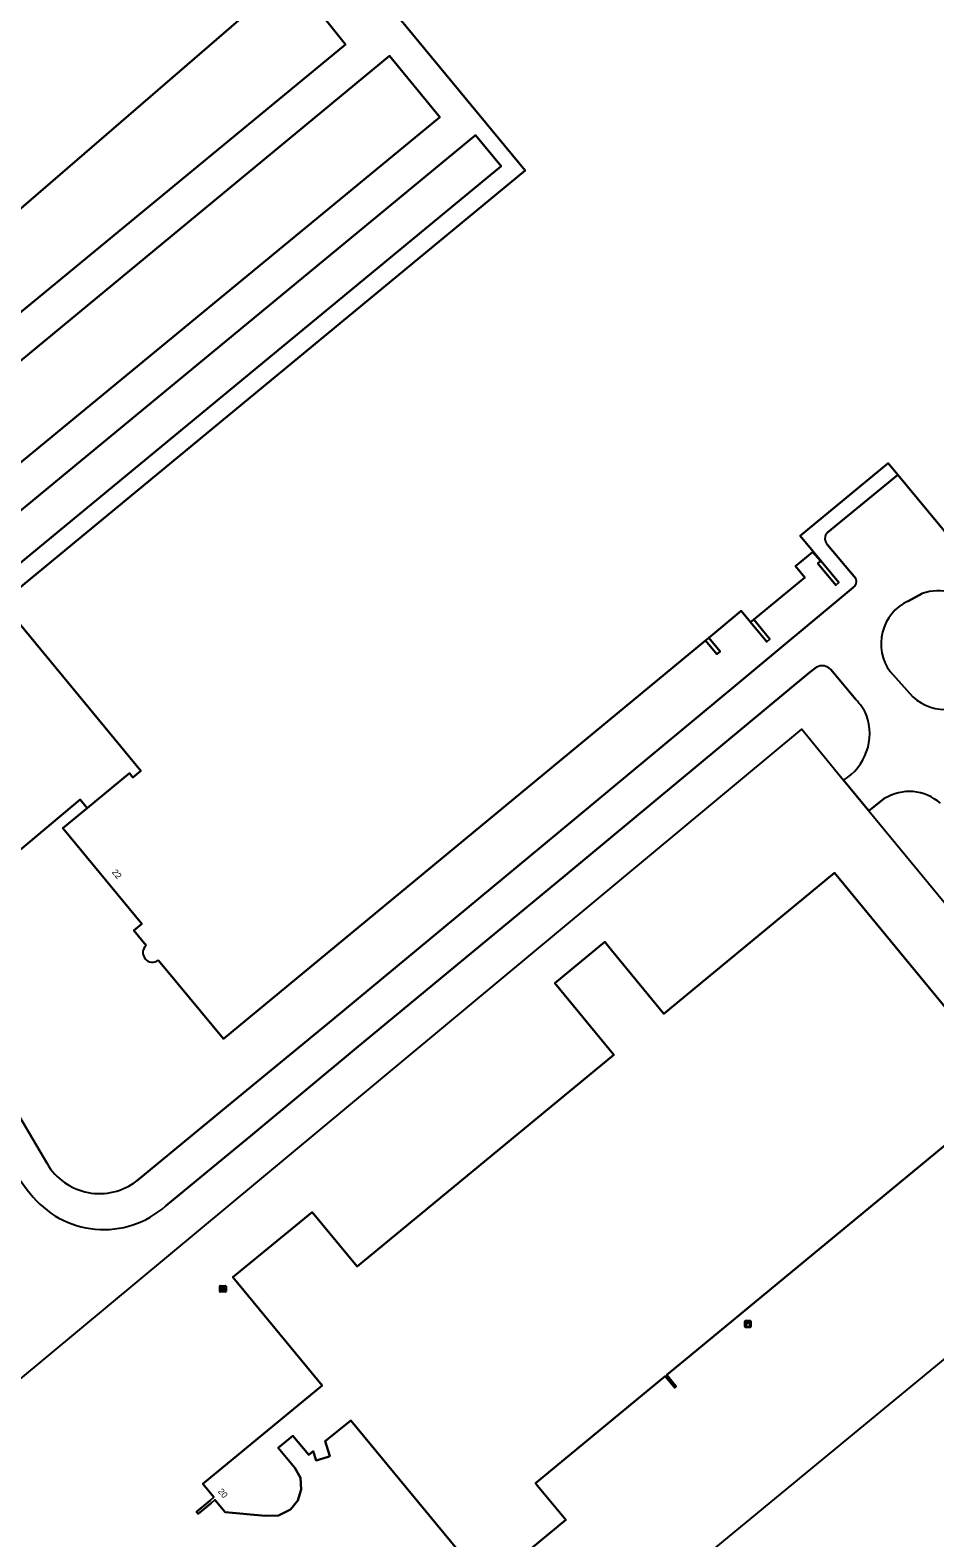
# Model space of a CAD drawing. Extents: x 156141 to 158132, y 385651 to 388333.
# Drawn here: x 156845.9 to 156991.8, y 386795.6 to 387038.6 of the extents above; entities that cross this region are included whole.
import ezdxf

# ---------------------------------------------------------------- set-up
doc = ezdxf.new("R2010")
doc.units = 0
for name, color, linetype in [('IMGEO_Brandkraan', 7, 'Continuous'), ('IMGEO_Erf', 7, 'Continuous'), ('IMGEO_Groenvoorziening', 7, 'Continuous'), ('IMGEO_Hek', 7, 'Continuous'), ('IMGEO_Kast', 7, 'Continuous'), ('IMGEO_Muur', 7, 'Continuous'), ('IMGEO_Pand', 7, 'Continuous'), ('IMGEO_Pand_nummerreeks', 7, 'Continuous'), ('IMGEO_Parkeervlak_open', 7, 'Continuous'), ('IMGEO_Rijbaan_lokaal_open', 7, 'Continuous')]:
    doc.layers.add(name, color=color, linetype=linetype)

msp = doc.modelspace()

# ---------------------------------------------------------------- linework, layer by layer
at = {"layer": 'IMGEO_Brandkraan'}
for p, q in [((156876.53, 386835.28), (156876.53, 386836.14)), ((156876.6, 386836.21), (156877.45, 386836.21)), ((156876.78, 386835.7), (156876.78, 386835.72)), ((156877.22, 386835.67), (156876.82, 386835.67)), ((156876.83, 386835.75), (156877.22, 386835.75)), ((156877.01, 386835.99), (156877.04, 386835.99)), ((156877.04, 386835.43), (156877.01, 386835.43)), ((156877.27, 386835.72), (156877.27, 386835.7)), ((156877.53, 386836.14), (156877.53, 386835.28)), ((156877.45, 386835.21), (156876.6, 386835.21))]:
    msp.add_line(p, q, dxfattribs=at)
for points in [[(156876.53, 386835.28), (156876.53, 386836.14)], [(156876.6, 386836.21), (156877.45, 386836.21)], [(156877.53, 386836.14), (156877.53, 386835.28)], [(156877.45, 386835.21), (156876.6, 386835.21)]]:
    msp.add_lwpolyline(points, dxfattribs=at)
for centre, radius, start, end in [((156876.6, 386836.13), 0.0765, 91.552, 178.448), ((156876.6, 386836.13), 0.0765, 91.552, 178.448), ((156876.82, 386835.71), 0.0403, 85.8775, 175.7526), ((156876.82, 386835.7), 0.0366, 178.938, 274.7102), ((156877.23, 386835.71), 0.0386, 1.7309, 96.639), ((156877.23, 386835.71), 0.043, 264.8664, 352.4533), ((156877.45, 386836.13), 0.0765, 1.552, 88.448), ((156877.45, 386836.13), 0.0765, 1.552, 88.448), ((156876.6, 386835.29), 0.0765, 181.552, 268.448), ((156876.6, 386835.29), 0.0765, 181.552, 268.448), ((156877.45, 386835.29), 0.0765, 271.552, 358.448), ((156877.45, 386835.29), 0.0765, 271.552, 358.448)]:
    msp.add_arc(centre, radius, start, end, dxfattribs=at)
for centre, major_axis, ratio, start_param, end_param in [((156877.01, 386835.71), (-0.387, 0.002), 0.722429, 4.712389, 7.853982), ((156877.04, 386835.71), (-0.39, 0.002), 0.717154, 1.570796, 4.712389)]:
    msp.add_ellipse(centre, major_axis=major_axis, ratio=ratio, start_param=start_param, end_param=end_param, dxfattribs=at)
at = {"layer": 'IMGEO_Erf'}
for points in [[(156812.2, 386966.59), (156822.21, 386974.91), (156848.13, 386996.22), (156874.15, 387017.66), (156896.78, 387036.3), (156892.3, 387041.9), (156921.3, 387066.08), (156921.52, 387066.27), (156984.63, 387118.63), (156988.71, 387113.85), (157030.87, 387062.8), (157072.84, 387097.37), (157078.51, 387102.05), (157050.66, 387135.79), (157053.95, 387138.53), (157054.32, 387138.82), (157047.16, 387147.09), (157045.59, 387148.77), (157045.55, 387148.73), (157039.88, 387154.84), (157004.35, 387193.14)], [(156911.85, 387068.09), (156832.99, 387000), (156800.99, 386972.36), (156777.18, 387000), (156772.74, 387005.15), (156771.43, 387004.01), (156770.43, 387005.17), (156768.59, 387007.3), (156767.67, 387008.37), (156769.03, 387009.55), (156758.46, 387021.81), (156761.82, 387024.7), (156759.18, 387027.76), (156756.89, 387025.86), (156755.46, 387027.58), (156757.7, 387029.56), (156754.18, 387033.58), (156759.17, 387037.94), (156766.82, 387029.07), (156787.07, 387046.56)], [(156985.85, 386966.92), (156984.29, 386968.8), (156970.11, 386957.1), (156972.21, 386954.56), (156976.35, 386949.55), (156975.85, 386949.14), (156972.96, 386952.65), (156973.36, 386952.98), (156972.12, 386954.48), (156969.35, 386952.21), (156970.86, 386950.37), (156962.62, 386943.58), (156965.24, 386940.42), (156964.73, 386939.99), (156962.12, 386943.17), (156960.62, 386945), (156955.39, 386940.67), (156957.19, 386938.45), (156956.69, 386938.03), (156956.67, 386938.03), (156954.85, 386940.24), (156877.1, 386876), (156867.98, 386887.02), (156866.6, 386888.69)], [(156974.52, 386957.63), (156985.85, 386966.92)], [(156979.08, 386950.2), (156974.53, 386955.63)], [(156863.16, 386853.13), (156877.89, 386865.29), (156894.76, 386879.12), (156928.37, 386906.98), (156959.67, 386932.97), (156978.65, 386948.75)], [(156972.76, 386935.91), (156971.62, 386935.07), (156932.21, 386902.35), (156898.5, 386874.49), (156881.84, 386860.65), (156867.81, 386849.08)], [(156979.07, 386930.69), (156975.05, 386935.56)], [(156981.2, 386912.78), (156977.12, 386917.72)], [(156864.67, 386891.04), (156862.64, 386893.47), (156863.96, 386894.55), (156851.23, 386909.97), (156855.14, 386913.21), (156854.02, 386914.57), (156827.12, 386892.07)], [(156983.67, 386914.73), (156981.2, 386912.78)], [(157000, 386864.22), (156951.3, 386824.08), (156948.6, 386821.85), (156949.64, 386820.58), (156950.13, 386819.99), (156949.88, 386819.78), (156948.84, 386821.04), (156948.34, 386821.64), (156929.53, 386806.11), (156927.98, 386804.84), (156927.43, 386804.38), (156927.76, 386803.98), (156932.31, 386798.47), (156919.56, 386787.95), (156897.63, 386814.52), (156893.52, 386811.17), (156894.29, 386808.74), (156893.81, 386808.6), (156892.06, 386808.06), (156891.59, 386809.57), (156890.86, 386808.97), (156888.3, 386812.04), (156885.94, 386810.09), (156888.62, 386806.85), (156889.51, 386805.23), (156889.65, 386803.37), (156889.11, 386801.59), (156887.93, 386800.14), (156885.99, 386799.18), (156883.82, 386799.14), (156877.37, 386799.74), (156875.72, 386801.68), (156875.13, 386801.19), (156873.03, 386799.46), (156872.77, 386799.79), (156874.95, 386801.6), (156875.58, 386802.11), (156873.77, 386804.26), (156893.03, 386820.11), (156878.65, 386837.58), (156891.41, 386848.1), (156898.65, 386839.3), (156940.06, 386873.42), (156930.54, 386884.98), (156938.6, 386891.63), (156939.7, 386890.29), (156948.14, 386880.06), (156949.1, 386880.85), (156975.66, 386902.77), (157000, 386873.24)], [(156826.64, 386886.09), (156828.46, 386883.87), (156832.98, 386878.61), (156837.97, 386872.1), (156842.98, 386865.6), (156848.66, 386855.9)]]:
    msp.add_lwpolyline(points, dxfattribs=at)
for centre, radius, start, end in [((156975.52, 386956.64), 1.41, 135.2917, 225.569), ((156978.05, 386949.72), 1.13, 301.7057, 25.3314), ((156973.66, 386934.17), 1.97, 45.0655, 117.3257), ((156973.32, 386924.8), 8.23, 24.4529, 45.7012), ((156972.53, 386925.23), 8.8, 301.4186, 19.7522), ((156987.7, 386908.28), 7.6, 48.4891, 121.992), ((156865.65, 386889.88), 1.52, 130.2522, 308.7836), ((156866.61, 386868.18), 26.82, 207.0033, 219.5816), ((156857.13, 386860.91), 9.84, 210.6182, 307.7776), ((156857.81, 386860.28), 15.01, 217.7294, 311.7585)]:
    msp.add_arc(centre, radius, start, end, dxfattribs=at)
at = {"layer": 'IMGEO_Groenvoorziening'}
for points in [[(156989.76, 386947.81), (156987.51, 386946.57)], [(156984.61, 386935.2), (156988.28, 386931.12)]]:
    msp.add_lwpolyline(points, dxfattribs=at)
for centre, radius, start, end in [((156992.38, 386939.83), 8.4, 42.4673, 108.2068), ((156990.72, 386939.7), 7.58, 115.0435, 216.3175), ((156993.52, 386936.89), 7.8, 227.7123, 324.5222)]:
    msp.add_arc(centre, radius, start, end, dxfattribs=at)
at = {"layer": 'IMGEO_Hek'}
for points in [[(156829.35, 386808.77), (156970.38, 386925.9), (156977.12, 386917.72)], [(156981.2, 386912.78), (157029.48, 386854.2)], [(157029.48, 386854.2), (156858.45, 386713.3)]]:
    msp.add_lwpolyline(points, dxfattribs=at)
at = {"layer": 'IMGEO_Kast'}
for p, q in [((156961.17, 386829.62), (156961.17, 386830.46)), ((156961.17, 386830.46), (156961.17, 386829.62)), ((156961.25, 386830.55), (156962.09, 386830.55)), ((156962.09, 386830.55), (156961.25, 386830.55)), ((156962.17, 386830.47), (156962.17, 386829.63)), ((156962.17, 386829.63), (156962.17, 386830.47)), ((156962.1, 386829.55), (156961.26, 386829.55)), ((156961.26, 386829.55), (156962.1, 386829.55))]:
    msp.add_line(p, q, dxfattribs=at)
for points in [[(156961.37, 386830.34), (156961.97, 386830.34), (156961.97, 386830.25), (156961.37, 386830.25), (156961.37, 386830.34)], [(156961.37, 386830.16), (156961.97, 386830.16), (156961.97, 386829.67), (156961.37, 386829.67), (156961.37, 386830.16)]]:
    msp.add_lwpolyline(points, dxfattribs=at)
msp.add_circle((156961.45, 386830.01), 0.0377, dxfattribs=at)
for centre, start, end in [((156961.25, 386830.47), 92.4484, 184.2845), ((156961.25, 386830.47), 92.4484, 184.2845), ((156962.09, 386830.47), 2.4484, 94.2845), ((156962.09, 386830.47), 2.4484, 94.2845), ((156961.25, 386829.63), 182.4484, 274.2845), ((156961.25, 386829.63), 182.4484, 274.2845), ((156962.09, 386829.63), 272.4484, 4.2845), ((156962.09, 386829.63), 272.4484, 4.2845)]:
    msp.add_arc(centre, 0.0779, start, end, dxfattribs=at)
at = {"layer": 'IMGEO_Muur'}
for points in [[(156972.21, 386954.56), (156972.12, 386954.48), (156973.36, 386952.98), (156972.96, 386952.65), (156975.85, 386949.14), (156976.35, 386949.55)], [(156962.62, 386943.58), (156962.12, 386943.17), (156964.73, 386939.99), (156965.24, 386940.42)], [(156955.39, 386940.67), (156954.85, 386940.24), (156956.67, 386938.03), (156956.69, 386938.03), (156957.19, 386938.45)]]:
    msp.add_lwpolyline(points, close=True, dxfattribs=at)
at = {"layer": 'IMGEO_Pand'}
for points in [[(157030.87, 387062.8), (156988.71, 387113.85), (156903.22, 387043.24), (156925.76, 387015.95), (156841.4, 386946.35), (156840.62, 386945.71), (156840.12, 386945.3), (156840.48, 386944.84), (156841.79, 386945.88), (156863.81, 386919.2), (156862.51, 386918.13), (156861.94, 386918.82), (156855.14, 386913.21), (156851.23, 386909.97), (156863.96, 386894.55), (156862.64, 386893.47), (156864.67, 386891.04)], [(156787.07, 387046.56), (156766.82, 387029.07), (156759.17, 387037.94), (156754.18, 387033.58), (156757.7, 387029.56), (156755.46, 387027.58), (156756.89, 387025.86), (156759.18, 387027.76), (156761.82, 387024.7), (156758.46, 387021.81), (156769.03, 387009.55), (156767.67, 387008.37), (156768.59, 387007.3), (156770.43, 387005.17), (156771.43, 387004.01), (156772.74, 387005.15), (156777.18, 387000), (156800.99, 386972.36), (156832.99, 387000), (156911.85, 387068.09)], [(156970.86, 386950.37), (156969.35, 386952.21), (156972.12, 386954.48), (156972.21, 386954.56), (156970.11, 386957.1), (156984.29, 386968.8), (156985.85, 386966.92), (156993.91, 386957.19)], [(156866.6, 386888.69), (156867.98, 386887.02), (156877.1, 386876), (156954.85, 386940.24), (156955.39, 386940.67), (156960.62, 386945), (156962.12, 386943.17), (156962.62, 386943.58), (156970.86, 386950.37)], [(157000, 386873.24), (156975.66, 386902.77), (156949.1, 386880.85), (156948.14, 386880.06), (156939.7, 386890.29), (156938.6, 386891.63), (156930.54, 386884.98), (156940.06, 386873.42), (156898.65, 386839.3), (156891.41, 386848.1), (156878.65, 386837.58), (156893.03, 386820.11), (156873.77, 386804.26), (156875.58, 386802.11), (156874.95, 386801.6), (156872.77, 386799.79), (156873.03, 386799.46), (156875.13, 386801.19), (156875.72, 386801.68), (156877.37, 386799.74), (156883.82, 386799.14), (156885.99, 386799.18), (156887.93, 386800.14), (156889.11, 386801.59), (156889.65, 386803.37), (156889.51, 386805.23), (156888.62, 386806.85), (156885.94, 386810.09), (156888.3, 386812.04), (156890.86, 386808.97), (156891.59, 386809.57), (156892.06, 386808.06), (156893.81, 386808.6), (156894.29, 386808.74), (156893.52, 386811.17), (156897.63, 386814.52), (156919.56, 386787.95), (156932.31, 386798.47), (156927.76, 386803.98), (156927.43, 386804.38), (156927.98, 386804.84), (156929.53, 386806.11), (156948.34, 386821.64), (156948.84, 386821.04), (156949.88, 386819.78), (156950.13, 386819.99), (156949.64, 386820.58), (156948.6, 386821.85), (156951.3, 386824.08), (157000, 386864.22)]]:
    msp.add_lwpolyline(points, dxfattribs=at)
msp.add_arc((156865.65, 386889.88), 1.52, 130.2522, 308.7836, dxfattribs=at)
at = {"layer": 'IMGEO_Parkeervlak_open'}
for points in [[(156903.87, 387034.43), (156821.33, 386966.25), (156821.33, 386964.88)], [(156831.44, 386958.25), (156912.01, 387024.58), (156903.87, 387034.43)]]:
    msp.add_lwpolyline(points, dxfattribs=at)
msp.add_lwpolyline([(156835.24, 386953.67), (156839.45, 386948.71), (156921.89, 387016.68), (156917.76, 387021.69)], close=True, dxfattribs=at)
at = {"layer": 'IMGEO_Rijbaan_lokaal_open'}
for points in [[(156827.12, 386892.07), (156854.02, 386914.57), (156855.14, 386913.21), (156861.94, 386918.82), (156862.51, 386918.13), (156863.81, 386919.2), (156841.79, 386945.88), (156840.48, 386944.84), (156840.12, 386945.3), (156840.62, 386945.71), (156841.4, 386946.35), (156925.76, 387015.95), (156903.22, 387043.24), (156988.71, 387113.85), (156984.63, 387118.63), (156921.52, 387066.27), (156921.3, 387066.08), (156892.3, 387041.9), (156896.78, 387036.3), (156874.15, 387017.66), (156848.13, 386996.22), (156822.21, 386974.91), (156812.2, 386966.59)], [(156821.33, 386964.88), (156821.33, 386966.25), (156903.87, 387034.43), (156912.01, 387024.58), (156831.44, 386958.25)], [(157002.98, 386925.56), (157008.33, 386929.92), (157014.26, 386929.42), (157016.15, 386930.98), (157013.61, 386934.06), (157019.18, 386938.65), (157016.64, 386942.01), (157063.43, 386981.12), (157049.67, 386997.8), (157018.3, 386971.93), (157019.81, 386967.53), (157019.76, 386954.38), (157011.99, 386947.65), (156999.93, 386962.16), (156993.91, 386957.19), (156985.85, 386966.92), (156974.52, 386957.63)], [(156974.53, 386955.63), (156979.08, 386950.2)], [(156978.65, 386948.75), (156959.67, 386932.97), (156928.37, 386906.98), (156894.76, 386879.12), (156877.89, 386865.29), (156863.16, 386853.13)], [(156987.51, 386946.57), (156989.76, 386947.81)], [(156867.81, 386849.08), (156881.84, 386860.65), (156898.5, 386874.49), (156932.21, 386902.35), (156971.62, 386935.07), (156972.76, 386935.91)], [(156975.05, 386935.56), (156979.07, 386930.69)], [(156988.28, 386931.12), (156984.61, 386935.2)], [(156977.12, 386917.72), (156981.2, 386912.78), (156983.67, 386914.73)], [(156848.66, 386855.9), (156842.98, 386865.6), (156837.97, 386872.1), (156832.98, 386878.61), (156828.46, 386883.87), (156826.64, 386886.09)]]:
    msp.add_lwpolyline(points, dxfattribs=at)
msp.add_lwpolyline([(156839.45, 386948.71), (156835.24, 386953.67), (156917.76, 387021.69), (156921.89, 387016.68)], close=True, dxfattribs=at)
for centre, radius, start, end in [((156975.52, 386956.64), 1.41, 135.2917, 225.569), ((156978.05, 386949.72), 1.13, 301.7057, 25.3314), ((156992.38, 386939.83), 8.4, 42.4673, 108.2068), ((156990.72, 386939.7), 7.58, 115.0435, 216.3175), ((156973.66, 386934.17), 1.97, 45.0655, 117.3257), ((156973.32, 386924.8), 8.23, 24.4529, 45.7012), ((156993.52, 386936.89), 7.8, 227.7123, 324.5222), ((156972.53, 386925.23), 8.8, 301.4186, 19.7522), ((156987.7, 386908.28), 7.6, 48.4891, 121.992), ((156866.61, 386868.18), 26.82, 207.0033, 219.5816), ((156857.13, 386860.91), 9.84, 210.6182, 307.7776), ((156857.81, 386860.28), 15.01, 217.7294, 311.7585)]:
    msp.add_arc(centre, radius, start, end, dxfattribs=at)

# ---------------------------------------------------------------- texts
at = {"layer": 'IMGEO_Pand_nummerreeks'}
for s, rotation, p in [('22', 309.5281, (156859.07, 386902.83)), ('20', 311.0592, (156876.16, 386803.01))]:
    msp.add_text(s, height=1, rotation=rotation, dxfattribs=at).set_placement(p)

doc.saveas('drawing.dxf')
